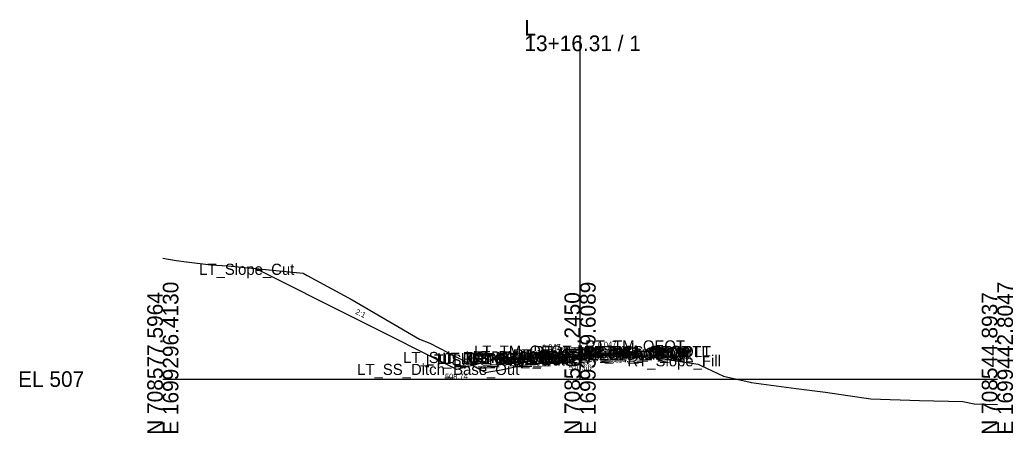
# Model space of a CAD drawing. Extents: x -63 to 1153, y -24 to 9522.
# Drawn here: x -25.7 to 152.8, y 3490.3 to 3564.5 of the extents above; entities that cross this region are included whole.
import ezdxf

# ---------------------------------------------------------------- set-up
doc = ezdxf.new("R2010")
doc.units = 0
for name, color, linetype in [('Default', 7, 'Continuous'), ('Exist Cross Section Cell', 7, 'Continuous'), ('Exist XS Center Line Elevation Label', 7, 'Continuous'), ('Exist XS Ground Line', 7, 'Continuous'), ('Prop CMT DNC', 7, 'Continuous'), ('Prop CMT Pvmt Course 1', 7, 'Continuous'), ('Prop CMT Pvmt Course 2', 7, 'Continuous'), ('Prop CMT Pvmt Surface', 7, 'Continuous'), ('Prop CMT Pvmt Surface Overlay', 7, 'Continuous'), ('Prop CMT Pvmt Surface Shoulder', 7, 'Continuous'), ('Prop CMT Shld Paved Course 1', 7, 'Continuous'), ('Prop CMT Shld Paved Course 2', 7, 'Continuous'), ('Prop CMT Slope Grass', 7, 'Continuous'), ('Prop CMT Subgrade Earthwork', 7, 'Continuous'), ('Prop XS Ditch Standard Text', 7, 'Continuous'), ('Prop XS Earthwork Shape', 7, 'Continuous'), ('Prop XS EOT Tick Mark', 7, 'Continuous'), ('Prop XS SE Text', 7, 'Continuous'), ('Prop XS Side Slope Text', 7, 'Continuous')]:
    doc.layers.add(name, color=color, linetype=linetype)

msp = doc.modelspace()

# ---------------------------------------------------------------- linework, layer by layer
at = {"layer": 'Exist Cross Section Cell'}
for p, q in [((75, 3500), (75, 3561.67)), ((0, 3500), (75, 3500)), ((75, 3500), (150, 3500))]:
    msp.add_line(p, q, dxfattribs=at)
at = {"layer": 'Exist XS Ground Line'}
msp.add_lwpolyline([(0, 3521.7), (2.38, 3521.31), (4.26, 3521.03), (8.61, 3520.53), (11.68, 3520.32), (25.2, 3519.02), (25.94, 3518.62), (34.03, 3514.21), (46.16, 3507.15), (48.01, 3506.44), (54.44, 3503.09), (58.06, 3501.2), (58.59, 3501.29), (60.82, 3501.64), (64.16, 3502.36), (65.41, 3502.63), (74.74, 3503.63), (75, 3503.66), (75.36, 3503.69), (84.75, 3504.32), (85.18, 3504.35), (85.97, 3504.24), (96.2, 3502.68), (96.68, 3502.43), (100.77, 3500.55), (105.57, 3499.46), (105.78, 3499.41), (113.87, 3498.31), (119.12, 3497.68), (123.1, 3497.04), (127.24, 3496.48), (136.01, 3496.18), (143.81, 3495.98), (145.82, 3495.54), (150, 3495.43)], dxfattribs=at)
at = {"layer": 'Prop CMT Pvmt Course 1'}
for points in [[(74.99, 3504.49), (84.99, 3504.96)], [(84.99, 3504.71), (74.99, 3504.24)], [(84.99, 3504.96), (84.99, 3504.71)], [(74.99, 3504.49), (64.99, 3504.02)], [(64.99, 3503.77), (74.99, 3504.24)], [(64.99, 3504.02), (64.99, 3503.77)], [(74.99, 3504.36), (74.99, 3504.49)], [(74.99, 3504.36), (74.99, 3504.49)], [(74.99, 3504.24), (74.99, 3504.36), (74.99, 3504.36)], [(74.99, 3504.24), (74.99, 3504.36), (74.99, 3504.36)]]:
    msp.add_lwpolyline(points, dxfattribs=at)
at = {"layer": 'Prop CMT Pvmt Course 2'}
for points in [[(74.99, 3504.24), (84.99, 3504.71)], [(84.99, 3504.71), (84.99, 3504.46)], [(74.99, 3504.24), (64.99, 3503.77)], [(64.99, 3503.52), (74.99, 3503.99)], [(64.99, 3503.77), (64.99, 3503.52)], [(84.99, 3504.46), (74.99, 3503.99)], [(74.99, 3503.99), (74.99, 3504.24)], [(74.99, 3503.99), (74.99, 3504.24)]]:
    msp.add_lwpolyline(points, dxfattribs=at)
at = {"layer": 'Prop CMT Pvmt Surface'}
for points in [[(74.99, 3504.49), (84.99, 3504.96)], [(74.99, 3504.49), (64.99, 3504.02)]]:
    msp.add_lwpolyline(points, dxfattribs=at)
at = {"layer": 'Prop CMT Pvmt Surface Overlay'}
for points in [[(74.99, 3504.49), (84.99, 3504.96)], [(74.99, 3504.49), (64.99, 3504.02)]]:
    msp.add_lwpolyline(points, dxfattribs=at)
at = {"layer": 'Prop CMT Pvmt Surface Shoulder'}
for points in [[(84.99, 3504.96), (85.13, 3504.96)], [(64.99, 3504.02), (63.6, 3503.96)]]:
    msp.add_lwpolyline(points, dxfattribs=at)
at = {"layer": 'Prop CMT Shld Paved Course 1'}
for points in [[(84.99, 3504.96), (85.13, 3504.96), (85.37, 3504.72)], [(84.99, 3504.71), (84.99, 3504.96)], [(85.37, 3504.72), (84.99, 3504.71)], [(64.99, 3504.02), (63.6, 3503.96), (63.34, 3503.69)], [(63.34, 3503.69), (64.99, 3503.77)], [(64.99, 3503.77), (64.99, 3504.02)]]:
    msp.add_lwpolyline(points, dxfattribs=at)
at = {"layer": 'Prop CMT Shld Paved Course 2'}
for points in [[(84.99, 3504.71), (85.37, 3504.72)], [(84.99, 3504.46), (84.99, 3504.71)], [(85.37, 3504.72), (85.37, 3504.72)], [(85.37, 3504.72), (85.61, 3504.49)], [(63.34, 3503.69), (63.08, 3503.43)], [(63.08, 3503.43), (64.99, 3503.52)], [(64.99, 3503.77), (63.34, 3503.69)], [(63.34, 3503.69), (63.34, 3503.69)], [(64.99, 3503.52), (64.99, 3503.77)], [(85.61, 3504.49), (84.99, 3504.46)]]:
    msp.add_lwpolyline(points, dxfattribs=at)
at = {"layer": 'Prop CMT Slope Grass'}
for points in [[(60.86, 3503.74), (52.86, 3501.74), (16.65, 3519.84)], [(85.13, 3504.96), (88.15, 3504.92)], [(88.15, 3504.92), (93.77, 3503.05)], [(63.6, 3503.96), (60.86, 3503.74)]]:
    msp.add_lwpolyline(points, dxfattribs=at)
at = {"layer": 'Prop CMT Subgrade Earthwork'}
for points in [[(85.61, 3504.49), (86.07, 3504.95)], [(63.08, 3503.43), (62.63, 3503.88)], [(64.99, 3503.52), (63.08, 3503.43)], [(74.99, 3503.99), (64.99, 3503.52)], [(74.99, 3503.99), (84.99, 3504.46)], [(84.99, 3504.46), (85.61, 3504.49)]]:
    msp.add_lwpolyline(points, dxfattribs=at)
at = {"layer": 'Prop XS Earthwork Shape'}
for points in [[(16.65, 3519.84), (25.2, 3519.02), (25.94, 3518.62), (34.03, 3514.21), (46.16, 3507.15), (48.01, 3506.44), (54.44, 3503.09), (55.68, 3502.44), (52.86, 3501.74)], [(64.99, 3503.52), (63.08, 3503.43), (62.63, 3503.88), (60.86, 3503.74), (55.68, 3502.44), (58.06, 3501.2), (58.59, 3501.29), (60.82, 3501.64), (64.16, 3502.36), (65.41, 3502.63), (74.74, 3503.63), (75, 3503.66), (75.36, 3503.69), (84.75, 3504.32), (85.18, 3504.35), (85.97, 3504.24), (93.77, 3503.05), (88.15, 3504.92), (86.07, 3504.95), (85.61, 3504.49), (84.99, 3504.46), (74.99, 3503.99)]]:
    msp.add_lwpolyline(points, close=True, dxfattribs=at)
at = {"layer": 'Prop XS EOT Tick Mark'}
for points in [[(64.99, 3504.02), (64.99, 3505.02)], [(84.99, 3504.96), (84.99, 3505.96)]]:
    msp.add_lwpolyline(points, dxfattribs=at)

# ---------------------------------------------------------------- texts
at = {"layer": 'Default'}
msp.add_text('-', height=0.0001, dxfattribs=at).set_placement((0, 3500))
at = {"layer": 'Exist Cross Section Cell'}
for s, p in [('L', (65, 3561.67)), ('13+16.31 / 1', (65, 3558.87)), ('EL 507', (-26, 3498.6))]:
    msp.add_text(s, height=2.8, dxfattribs=at).set_placement(p)
for s, p in [('E 1699296.4130', (2.8, 3490)), ('E 1699369.6089', (77.8, 3490)), ('E 1699442.8047', (152.8, 3490)), ('N 708577.5964', (0, 3490)), ('N 708561.2450', (75, 3490)), ('N 708544.8937', (150, 3490))]:
    msp.add_text(s, height=2.8, rotation=90, dxfattribs=at).set_placement(p)
at = {"layer": 'Exist XS Center Line Elevation Label'}
msp.add_text('510.66', height=1, dxfattribs=at).set_placement((72.98, 3501.61))
at = {"layer": 'Prop CMT DNC'}
for s, p in [('LT_Slope_Cut', (6.54, 3518.71)), ('RT_TM_OEOT', (75.89, 3504.96)), ('LT_Sub_Trench_Out_DLT', (43.2, 3502.88)), ('LT_PS2_Shelf_Out', (49.32, 3502.69)), ('LT_GS_OS_CTL', (50.23, 3502.74)), ('LT_PS2_OEOP', (53.57, 3502.69)), ('LT_PS1_OEOP', (54.4, 3502.96)), ('LT_Sub_OEOT', (55.07, 3502.52)), ('LT_PV2_OEOT', (55.17, 3502.77)), ('LT_PV1_OEOT', (55.74, 3503.02)), ('LT_TM_OEOT', (55.94, 3504.02)), ('RT_PV1_OEEOP_W', (62.93, 3503.36)), ('LT_PV1_OEEOP_W', (62.98, 3503.36)), ('RT_Sub_OEEOP', (64.16, 3502.99)), ('LT_Sub_OEEOP', (64.21, 3502.99)), ('RT_PV2_OEEOP', (64.25, 3503.24)), ('LT_PV2_OEEOP', (64.3, 3503.24)), ('RT_Sub_Trench_Out_DLT', (66.59, 3503.95)), ('PV1_PGL_W', (67.58, 3503.36)), ('PV1_PGL', (69.47, 3503.49)), ('RT_Sub_Trench_Out', (69.77, 3503.49)), ('RT_PS2_Shelf_Out', (71.31, 3503.72)), ('RT_Sub_OEOT', (75.03, 3503.46)), ('RT_PV2_OEOT', (75.12, 3503.71)), ('RT_PS2_OEOP', (75.56, 3503.72)), ('RT_PV1_OEOT', (75.69, 3503.96)), ('RT_PS1_OEOP', (75.89, 3503.96)), ('RT_GS_OS_CTL', (77.47, 3503.92)), ('LT_SS_Ditch_Base_Out', (34.94, 3500.74)), ('LT_Sub_Trench_Out', (47.28, 3502.43)), ('RT_Slope_Fill', (83.52, 3502.29))]:
    msp.add_text(s, height=2, dxfattribs=at).set_placement(p)
at = {"layer": 'Prop XS Ditch Standard Text'}
msp.add_text('508.74', height=1, dxfattribs=at).set_placement((50.72, 3499.99))
at = {"layer": 'Prop XS SE Text'}
for p in [(78.2, 3505.64), (68.2, 3505.17)]:
    msp.add_text('0.047', height=1, rotation=2.6821, dxfattribs=at).set_placement(p)
at = {"layer": 'Prop XS Side Slope Text'}
for s, rotation, p in [('2:1', 333.4349, (34.51, 3511.75)), ('4:1', 14.0363, (55.91, 3503.27)), ('3:1', 341.5659, (90.08, 3505.07))]:
    msp.add_text(s, height=1, rotation=rotation, dxfattribs=at).set_placement(p)

doc.saveas('drawing.dxf')
